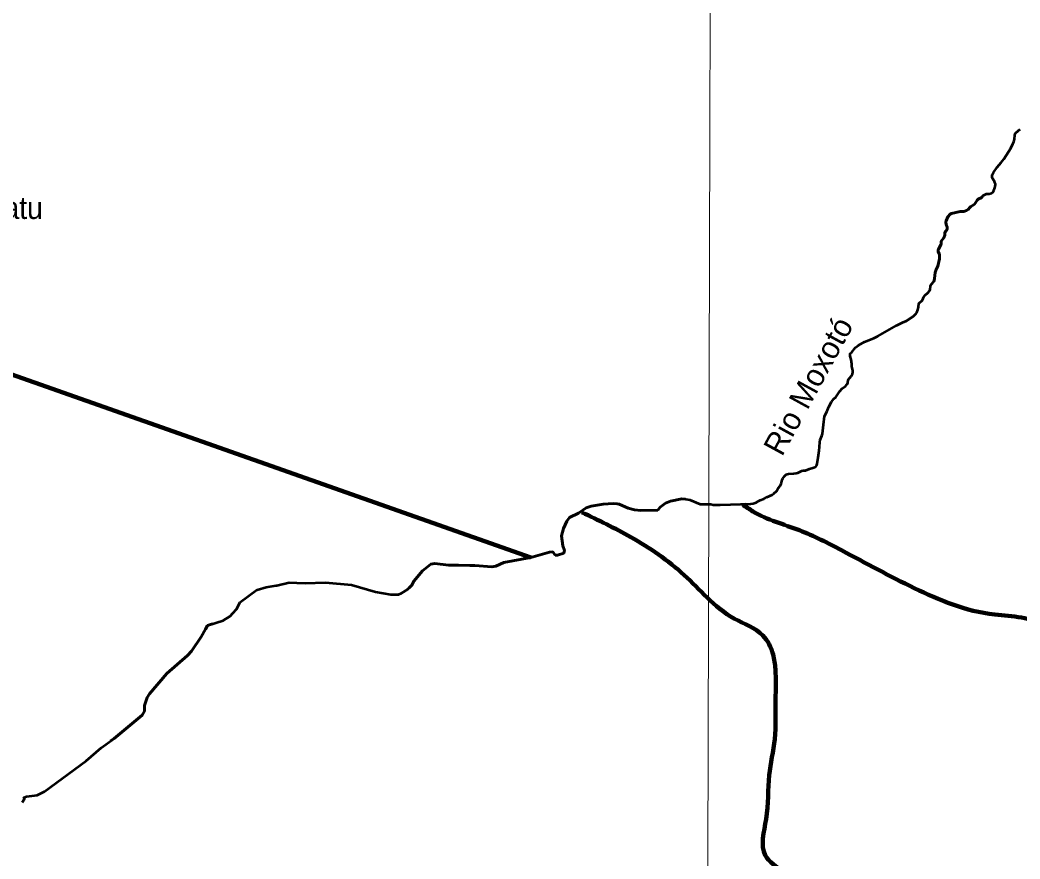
# Model space of a CAD drawing. Extents: x 553962 to 842807, y 8883888 to 9032388.
# Drawn here: x 594396 to 616862, y 8979846 to 8998684 of the extents above; entities that cross this region are included whole.
import ezdxf
from ezdxf.enums import TextEntityAlignment as Align

# ---------------------------------------------------------------- set-up
doc = ezdxf.new("R2010")
doc.units = 0
doc.header["$LTSCALE"] = 200
doc.linetypes.add('LONG_DASH_SHORT_DASH', pattern=[9.9, 6, -1.2, 1.5, -1.2])
for name, color, linetype, lineweight in [('1', 7, 'Continuous', 13), ('24', 7, 'Continuous', 25), ('7', 7, 'LONG_DASH_SHORT_DASH', 60), ('9', 7, 'Continuous', 90)]:
    doc.layers.add(name, color=color, linetype=linetype, lineweight=lineweight)
doc.layers.add('41', color=7, linetype='Continuous')
doc.layers.add('49', color=7, linetype='Continuous')

msp = doc.modelspace()

# ---------------------------------------------------------------- linework, layer by layer
at = {"layer": '1'}
msp.add_lwpolyline([(609971.9, 9023551.8), (609764.7, 8949706.7), (609734.2, 8939404.4)], dxfattribs=at)
at = {"layer": '24', "lineweight": 53}
for points in [[(616275, 8994855), (616299.8, 8994916), (616306.6, 8994947), (616309.5, 8994997), (616289.9, 8995061), (616239.9, 8995143), (616235.6, 8995179), (616237.4, 8995206), (616262.8, 8995260), (616352.4, 8995378.9), (616439.6, 8995482.9), (616497.8, 8995558.9), (616654.6, 8995808.9), (616704.2, 8995904.9), (616721.4, 8995949.9), (616734.9, 8996009.9), (616742.4, 8996094.9), (616755.2, 8996130.9), (616770.5, 8996150.9), (616865.5, 8996231.9)], [(615088.6, 8993660), (615092.1, 8993720), (615153, 8993790), (615174.6, 8993852), (615175.1, 8993904), (615179, 8993921), (615187.3, 8993934), (615211.5, 8993958), (615228.8, 8993992), (615227.7, 8994030), (615203.4, 8994096), (615199.3, 8994145), (615206.1, 8994178), (615239.1, 8994264), (615295.5, 8994325), (615320, 8994336), (615520.9, 8994382), (615601.5, 8994383), (615661.9, 8994403), (615699.6, 8994431), (615734.4, 8994474), (615755.4, 8994494), (615812.3, 8994527), (615840.8, 8994550), (615864.4, 8994578), (615900.1, 8994637), (615919.4, 8994659), (615934.8, 8994670), (615988.9, 8994692), (616008.8, 8994710), (616037.3, 8994745), (616076.4, 8994766), (616108.6, 8994778), (616169.1, 8994784), (616218.9, 8994795), (616250.2, 8994821), (616275, 8994855)], [(612374.7, 8989257.2), (612410.1, 8989349.2), (612422.8, 8989393.2), (612443.9, 8989595.2), (612472.1, 8989790.2), (612521.4, 8989889.2), (612567.7, 8990001.2), (612623.5, 8990108.2), (612679.4, 8990175.2), (612720.8, 8990217.2), (612815.3, 8990351.2), (612864.4, 8990407.2), (612937.9, 8990460.2), (612974.6, 8990496.2), (612997.1, 8990536.2), (613004.6, 8990605.2), (613071.9, 8990685.2), (613099.4, 8990741.2), (613104.8, 8990769.2), (613104.8, 8990813.2), (613086.3, 8990905.2), (613085.9, 8990954.2), (613066.1, 8991064.2), (613044.7, 8991133.2), (613043.4, 8991164.2), (613047.9, 8991196.2), (613081.7, 8991228.2), (613169.8, 8991332.2), (613227.7, 8991376.2), (613365.8, 8991458.1), (613579.6, 8991541.1), (613666.1, 8991582.1), (614090.8, 8991825.1), (614218.9, 8991891.1), (614310.9, 8991932.1), (614460.7, 8992023.1), (614532.5, 8992094.1), (614543.7, 8992113.1), (614569, 8992177.1), (614582, 8992234.1), (614589.2, 8992317.1), (614668.2, 8992394.1), (614704.5, 8992469.1), (614728, 8992505.1), (614788.8, 8992558.1), (614827.1, 8992602.1), (614841.2, 8992635.1), (614852.2, 8992705.1), (614861.2, 8992733.1), (614874, 8992755.1), (614920, 8992803.1), (614934.5, 8992832.1), (614943.5, 8992879.1), (614957.9, 8993016), (614981.1, 8993081), (615017.2, 8993154), (615053.5, 8993321), (615053.4, 8993409), (615046.2, 8993436), (615020.3, 8993489), (615020.7, 8993515), (615030.5, 8993541), (615082.9, 8993633), (615082.9, 8993633), (615088.6, 8993660)], [(610812.6, 8987820.3), (610868.6, 8987825.3), (610933, 8987849.3), (611023.7, 8987905.3), (611105.7, 8987931.3), (611174.3, 8987972.3), (611295.8, 8988024.3), (611334, 8988050.3), (611392.2, 8988106.3), (611428.2, 8988171.3), (611476.2, 8988225.3), (611496.6, 8988270.3), (611519.8, 8988356.3), (611535.1, 8988392.3), (611570.6, 8988443.3), (611611.3, 8988477.3), (611633.5, 8988486.3), (611663.2, 8988493.3), (611778.5, 8988500.3), (611831.3, 8988507.2), (611867.2, 8988517.2), (611960.5, 8988564.2), (611993.5, 8988570.2), (612040.4, 8988571.2), (612135.1, 8988609.2), (612211, 8988629.2), (612253, 8988646.2), (612280.4, 8988668.2), (612294.2, 8988690.2), (612304.8, 8988723.2), (612325, 8988861.2), (612344.1, 8988963.2), (612347.8, 8989019.2), (612358.9, 8989089.2), (612362.3, 8989210.2), (612374.7, 8989257.2)], [(608722.9, 8987680.8), (608777.9, 8987747.6), (608897.1, 8987833.6), (609009.5, 8987880.2), (609264.4, 8987935.4), (609356.3, 8987924.6)], [(609356.3, 8987924.6), (609448.1, 8987913.7), (609678.6, 8987816.5)], [(606420.8, 8986668), (606473.8, 8986668.1), (606613.3, 8986714.2), (606626.1, 8986769), (606594.2, 8986880), (606564.5, 8987100.6), (606609.1, 8987266.3), (606681.2, 8987431.8), (606741, 8987512.8), (606939.6, 8987610), (607118.9, 8987727.3), (607224.8, 8987767.6), (607501, 8987816.5), (607722.2, 8987831.4), (607811.1, 8987818.7)], [(607811.1, 8987818.7), (607857.5, 8987812), (608058.1, 8987723), (608202.2, 8987682.7), (608346.4, 8987672.1), (608722.9, 8987680.8)], [(609678.6, 8987816.5), (609919.3, 8987814.4), (609966, 8987801.4), (610032.6, 8987795.3), (610127.9, 8987794.3), (610812.6, 8987820.3)], [(604502.8, 8986438.7), (604614.5, 8986437.8), (604995.5, 8986406.1), (605088.3, 8986418.9), (605266.8, 8986501.7), (605873.8, 8986618.4), (606294.7, 8986737.4), (606369.1, 8986745.7), (606420.8, 8986668)], [(603138.8, 8985934.3), (603201.3, 8985995.2), (603246.4, 8986085.3), (603439.7, 8986316.8), (603622.3, 8986468.1), (603715.8, 8986478.2), (604022, 8986442.1), (604249.4, 8986440.5), (604502.8, 8986438.7)], [(599176.5, 8985365.4), (599258.9, 8985456.2), (599344, 8985609.2), (599718.7, 8985887.4)], [(599718.7, 8985887.4), (599721.5, 8985889.5), (599926.2, 8985947.2), (600149.2, 8985983.3), (600164.2, 8985987.1)], [(600164.2, 8985987.1), (600446.9, 8986057.4), (600614.3, 8986048.6)], [(600614.3, 8986048.6), (600805.6, 8986038.6), (601260, 8986057.6), (601842, 8986004.5), (602386.1, 8985845.2), (602725.9, 8985781.5), (602895.9, 8985787.9), (602963.8, 8985811.2), (603100.1, 8985896.5), (603138.8, 8985934.3)], [(598562.6, 8985004.4), (598611, 8985091.4), (598961, 8985203.4), (599114.5, 8985297), (599176.5, 8985365.4)], [(597241.4, 8983430.3), (597255.2, 8983474), (597303.8, 8983551.2), (597693.6, 8984012), (598158.8, 8984413.5), (598250.1, 8984513.3), (598466.9, 8984832.2), (598562.6, 8985004.4)], [(597144.4, 8983071.7), (597192.6, 8983165.7), (597196.6, 8983289.5), (597241.4, 8983430.3)], [(594445, 8981112.5), (594498.6, 8981193.2), (594478.9, 8981228.6), (594539.1, 8981252.5), (594781.2, 8981282.3), (594943.8, 8981357.5), (595881.6, 8982053.4), (596221.2, 8982344.2), (596509.3, 8982553.5), (597144.4, 8983071.7)]]:
    msp.add_lwpolyline(points, dxfattribs=at)
at = {"layer": '7', "lineweight": 35}
msp.add_line((610685.7, 8987847), (610687.2, 8987846.5), dxfattribs=at)
at = {"layer": '7'}
msp.add_line((603104.5, 8985900.8), (603138.8, 8985934.3), dxfattribs=at)
for points in [[(615088.6, 8993660), (615092.1, 8993720), (615153, 8993790), (615174.6, 8993852), (615175.1, 8993904), (615179, 8993921), (615187.3, 8993934), (615211.5, 8993958), (615228.8, 8993992), (615227.7, 8994030), (615203.4, 8994096), (615199.3, 8994145), (615206.1, 8994178), (615239.1, 8994264), (615295.5, 8994325), (615320, 8994336), (615520.9, 8994382), (615601.5, 8994383), (615661.9, 8994403), (615699.6, 8994431), (615734.4, 8994474), (615755.4, 8994494), (615812.3, 8994527), (615840.8, 8994550), (615864.4, 8994578), (615900.1, 8994637), (615919.4, 8994659), (615934.8, 8994670), (615988.9, 8994692), (616008.8, 8994710), (616037.3, 8994745)], [(614923.2, 8992809.3), (614934.5, 8992832.1), (614943.5, 8992879.1), (614957.9, 8993016), (614981.1, 8993081), (615017.2, 8993154), (615053.5, 8993321), (615053.4, 8993409), (615046.2, 8993436), (615020.3, 8993489), (615020.7, 8993515), (615030.5, 8993541), (615082.9, 8993633), (615082.9, 8993633), (615088.6, 8993660)], [(608722.9, 8987680.8), (608777.9, 8987747.6), (608897.1, 8987833.6), (609009.5, 8987880.2), (609264.4, 8987935.4), (609347, 8987925.7)], [(606420.8, 8986668), (606473.8, 8986668.1), (606613.3, 8986714.2), (606626.1, 8986769), (606594.2, 8986880), (606564.5, 8987100.6), (606609.1, 8987266.3), (606681.2, 8987431.8), (606741, 8987512.8), (606939.6, 8987610), (607118.9, 8987727.3), (607224.8, 8987767.6), (607501, 8987816.5), (607722.2, 8987831.4), (607811.1, 8987818.7)], [(607811.1, 8987818.7), (607857.5, 8987812), (608058.1, 8987723), (608202.2, 8987682.7), (608346.4, 8987672.1), (608722.9, 8987680.8)], [(604502.8, 8986438.7), (604614.5, 8986437.8), (604995.5, 8986406.1), (605088.3, 8986418.9), (605266.8, 8986501.7), (605873.8, 8986618.4), (606294.7, 8986737.4), (606369.1, 8986745.7), (606420.8, 8986668)], [(603138.8, 8985934.3), (603201.3, 8985995.2), (603246.4, 8986085.3), (603439.7, 8986316.8), (603622.3, 8986468.1), (603715.8, 8986478.2), (604022, 8986442.1), (604249.4, 8986440.5), (604502.8, 8986438.7)], [(597241.4, 8983430.3), (597255.2, 8983474), (597303.8, 8983551.2), (597693.6, 8984012), (598158.8, 8984413.5), (598250.1, 8984513.3), (598466.9, 8984832.2), (598562.6, 8985004.4)], [(598562.6, 8985004.4), (598611, 8985091.4), (598722.8, 8985127.2)], [(597144.4, 8983071.7), (597192.6, 8983165.7), (597196.6, 8983289.5), (597241.4, 8983430.3)], [(596432.2, 8982497.4), (596509.3, 8982553.5), (597144.4, 8983071.7)]]:
    msp.add_lwpolyline(points, dxfattribs=at)
at = {"layer": '9'}
msp.add_lwpolyline([(605873.8, 8986618.4), (590956.6, 8991866.7), (589163, 9005713.7)], dxfattribs=at)
for points in [[(623791.9, 8983133), (622543.6, 8983352), (621651, 8983674.8), (620351.1, 8984020), (620094.1, 8984448.6), (619305.4, 8984417.7), (618517.6, 8984234.9), (617956.8, 8984382.8), (617392.9, 8985062.3), (616297.1, 8985333.1), (614486.7, 8985927.8), (612853, 8986777), (611908.8, 8987226), (610862.9, 8987648.9), (610631.7, 8987802.8)], [(607019.9, 8987628.8), (608117.9, 8987072.5), (609319, 8986220.3), (609831, 8985717.6), (610444.6, 8985240.9), (611083, 8984865.7), (611314.6, 8984437), (611367.4, 8984108.2), (611371.5, 8983424.7), (611351.3, 8982538.5), (611228.8, 8981727.5), (611158.3, 8980739.6), (611137.7, 8979929.4), (611547.1, 8979552.5), (611828.5, 8979301.3), (612340.6, 8978773.3), (612648.8, 8978294.5), (612832.8, 8977308.5), (612940.5, 8976321.9), (612949.5, 8974803), (612829.3, 8973612.2), (613105.4, 8971372.7), (613572.8, 8968712.3), (614200.8, 8967292.3), (614110, 8965907), (613645.9, 8964639.4)]]:
    msp.add_spline(points, degree=3, dxfattribs=at)

# ---------------------------------------------------------------- texts
at = {"layer": '41', "width": 0.95}
msp.add_text('Tacaratu', height=500, dxfattribs=at).set_placement((592402.2, 8994216.5))
at = {"layer": '49'}
msp.add_text('Rio Moxotó', height=500, rotation=61.364, dxfattribs=at).set_placement((612325.1, 8990347.9), align=Align.CENTER)

doc.saveas('drawing.dxf')
